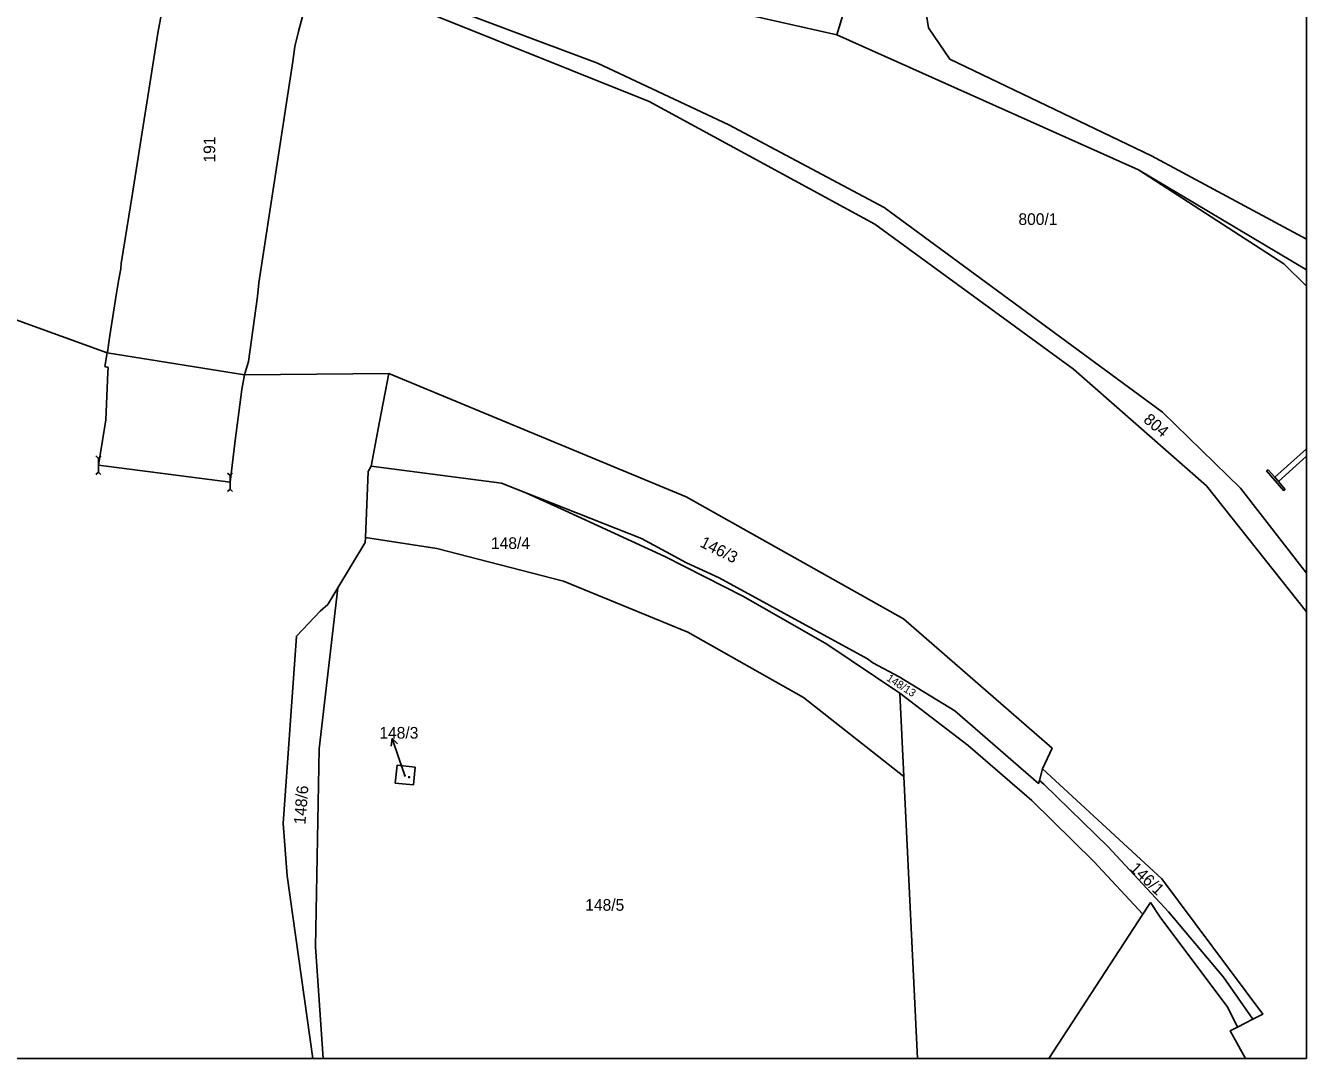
# Model space of a CAD drawing. Extents: x -598934 to -598196, y -1162208 to -1161502.
# Drawn here: x -598382.2 to -598195.6, y -1162207 to -1162056.4 of the extents above; entities that cross this region are included whole.
import ezdxf

# ---------------------------------------------------------------- set-up
doc = ezdxf.new("R2010")
doc.units = 0
for name, color, linetype in [('KN_CAR_KR', 7, 'Continuous'), ('KN_KULTURY', 7, 'Continuous'), ('KN_PARC_CIS_POM', 7, 'Continuous'), ('KN_PARC_CIS_POZ', 7, 'Continuous'), ('KN_PARC_CIS_STAV', 7, 'Continuous'), ('KN_PARC_PLOCHA', 7, 'Continuous'), ('PARC_C_SIPKA', 7, 'Continuous'), ('parcely_l', 7, 'Continuous')]:
    doc.layers.add(name, color=color, linetype=linetype)

msp = doc.modelspace()

# ---------------------------------------------------------------- linework, layer by layer
at = {"layer": 'KN_CAR_KR'}
for points in [[(-598220.05, -1162077.44), (-598198.85, -1162091.15)], [(-598198.85, -1162091.15), (-598195.56, -1162094.37)], [(-598370.68, -1162106.09), (-598370.34, -1162104.09)], [(-598370.22, -1162106.23), (-598370.68, -1162106.09)], [(-598370.53, -1162113.86), (-598370.27, -1162106.96)], [(-598370.27, -1162106.96), (-598370.22, -1162106.23)], [(-598350.7, -1162109.47), (-598350.35, -1162107.33)], [(-598351.7, -1162116.9), (-598350.7, -1162109.47)], [(-598370.53, -1162113.86), (-598370.72, -1162115.08)], [(-598370.72, -1162115.08), (-598371.63, -1162120.5)], [(-598352.44, -1162122.98), (-598351.7, -1162116.9)], [(-598195.56, -1162118.09), (-598200.16, -1162122.25)], [(-598371.63, -1162120.5), (-598352.44, -1162122.98)], [(-598199.63, -1162122.86), (-598195.56, -1162119.16)], [(-598201.39, -1162121.32), (-598201.11, -1162121.18)], [(-598198.86, -1162124.21), (-598201.39, -1162121.32)], [(-598201.11, -1162121.18), (-598200.16, -1162122.25)], [(-598200.16, -1162122.25), (-598199.63, -1162122.86)], [(-598199.63, -1162122.86), (-598198.65, -1162124.02)], [(-598198.65, -1162124.02), (-598198.86, -1162124.21)]]:
    msp.add_lwpolyline(points, dxfattribs=at)
at = {"layer": 'KN_KULTURY'}
for p, q in [((-598371.63, -1162121.5), (-598371.63, -1162119.5)), ((-598352.44, -1162123.98), (-598352.44, -1162121.98))]:
    msp.add_line(p, q, dxfattribs=at)
for points in [[(-598371.98, -1162119.15), (-598371.63, -1162119.5), (-598371.28, -1162119.15)], [(-598371.98, -1162121.85), (-598371.63, -1162121.5), (-598371.28, -1162121.85)], [(-598352.79, -1162121.63), (-598352.44, -1162121.98), (-598352.09, -1162121.63)], [(-598352.79, -1162124.33), (-598352.44, -1162123.98), (-598352.09, -1162124.33)]]:
    msp.add_lwpolyline(points, dxfattribs=at)
for radius in [0.09, 0.0398]:
    msp.add_circle((-598326.33, -1162165.97), radius, dxfattribs=at)
at = {"layer": 'KN_PARC_PLOCHA'}
for points in [[(-598195.56, -1162087.55), (-598218.14, -1162075.38), (-598247.54, -1162061.32), (-598250.65, -1162056.75), (-598252, -1162047.98), (-598239.76, -1162045.66), (-598222.81, -1162042.25), (-598205.98, -1162037.63), (-598195.56, -1162034.22)], [(-598263.99, -1162057.76), (-598220.05, -1162077.44), (-598195.56, -1162092.01), (-598195.56, -1162136.23), (-598205.15, -1162123.82), (-598216.54, -1162112.76), (-598257.11, -1162082.94), (-598279.75, -1162070.87), (-598298.86, -1162061.88), (-598339.73, -1162046.53), (-598339.66, -1162046.05), (-598338.47, -1162039.46), (-598331.32, -1162040.94), (-598316.47, -1162043.58), (-598304.18, -1162046.54), (-598295.91, -1162047.3), (-598291.83, -1162048.73), (-598287.23, -1162050.26), (-598284.77, -1162051.1), (-598282.25, -1162051.96), (-598279.39, -1162053.09), (-598278.46, -1162054.52)], [(-598195.56, -1162136.23), (-598195.56, -1162141.85), (-598210.14, -1162123.52), (-598229.5, -1162106.51), (-598258.47, -1162085.36), (-598291.34, -1162067.48), (-598324.91, -1162054), (-598340.53, -1162050.35), (-598339.73, -1162046.53), (-598298.86, -1162061.88), (-598279.75, -1162070.87), (-598257.11, -1162082.94), (-598216.54, -1162112.76), (-598205.15, -1162123.82)], [(-598195.56, -1162087.55), (-598195.56, -1162092.01), (-598220.05, -1162077.44), (-598263.99, -1162057.76), (-598261.41, -1162049.25), (-598252, -1162047.98), (-598250.65, -1162056.75), (-598247.54, -1162061.32), (-598218.14, -1162075.38)], [(-598234, -1162164.77), (-598234.47, -1162166.45), (-598234.59, -1162166.88), (-598246.81, -1162156.31), (-598254.92, -1162151.32), (-598258.74, -1162149.32), (-598259.51, -1162148.74), (-598281.14, -1162136.91), (-598285.89, -1162134.72), (-598292.46, -1162131.16), (-598309.31, -1162124.51), (-598312.87, -1162123.1), (-598331.85, -1162120.61), (-598330.66, -1162114.17), (-598329.28, -1162107.14), (-598285.97, -1162125.12), (-598254.28, -1162142.9), (-598232.63, -1162161.76)], [(-598309.31, -1162124.51), (-598303.63, -1162127.1), (-598289.09, -1162133.8), (-598277.62, -1162139.65), (-598265.44, -1162146.56), (-598254.82, -1162153.71), (-598254.23, -1162165.87), (-598268.85, -1162154.33), (-598285.74, -1162144.81), (-598303.83, -1162137.38), (-598322.31, -1162132.64), (-598332.7, -1162131.01), (-598332.32, -1162121.43), (-598331.85, -1162120.61), (-598312.87, -1162123.1)], [(-598234.47, -1162166.45), (-598233.83, -1162166.99), (-598224.46, -1162176.14), (-598215.64, -1162185.62), (-598207.62, -1162195.12), (-598203.37, -1162201.25), (-598205.62, -1162202.39), (-598207.02, -1162199.53), (-598216.85, -1162186.38), (-598218.3, -1162184.26), (-598219.4, -1162185.95), (-598226.54, -1162178.27), (-598235.59, -1162169.37), (-598244.87, -1162161.35), (-598254.82, -1162153.71), (-598265.44, -1162146.56), (-598277.62, -1162139.65), (-598289.09, -1162133.8), (-598303.63, -1162127.1), (-598309.31, -1162124.51), (-598292.46, -1162131.16), (-598285.89, -1162134.72), (-598281.14, -1162136.91), (-598259.51, -1162148.74), (-598258.74, -1162149.32), (-598254.92, -1162151.32), (-598246.81, -1162156.31), (-598234.59, -1162166.88)], [(-598254.23, -1162165.87), (-598252.26, -1162206.96), (-598338.86, -1162206.96), (-598339.99, -1162190.7), (-598339.45, -1162161.86), (-598336.71, -1162138.36), (-598332.73, -1162131.76), (-598332.7, -1162131.01), (-598322.31, -1162132.64), (-598303.83, -1162137.38), (-598285.74, -1162144.81), (-598268.85, -1162154.33)], [(-598338.86, -1162206.96), (-598340.39, -1162206.96), (-598344.1, -1162180.34), (-598344.68, -1162172.7), (-598342.77, -1162145.4), (-598339.32, -1162141.77), (-598338.19, -1162140.82), (-598336.71, -1162138.36), (-598339.45, -1162161.86), (-598339.99, -1162190.7)], [(-598219.4, -1162185.95), (-598233.08, -1162206.96), (-598252.26, -1162206.96), (-598254.23, -1162165.87), (-598254.82, -1162153.71), (-598244.87, -1162161.35), (-598235.59, -1162169.37), (-598226.54, -1162178.27)], [(-598325.47, -1162164.5), (-598325.72, -1162167.09), (-598328.36, -1162166.82), (-598328.1, -1162164.23)], [(-598325.47, -1162164.5), (-598328.1, -1162164.23), (-598328.36, -1162166.82), (-598325.72, -1162167.09)], [(-598203.37, -1162201.25), (-598207.62, -1162195.12), (-598215.64, -1162185.62), (-598224.46, -1162176.14), (-598233.83, -1162166.99), (-598234.47, -1162166.45), (-598234, -1162164.77), (-598216.64, -1162180.77), (-598201.91, -1162200.52)], [(-598205.62, -1162202.39), (-598206.66, -1162202.95), (-598204.42, -1162206.96), (-598233.08, -1162206.96), (-598219.4, -1162185.95), (-598218.3, -1162184.26), (-598216.85, -1162186.38), (-598207.02, -1162199.53)]]:
    msp.add_lwpolyline(points, close=True, dxfattribs=at)
for points in [[(-598406.5, -1162041.96), (-598368.98, -1162046.88), (-598369.04, -1162047.3), (-598369.12, -1162047.84), (-598369.89, -1162052.52), (-598362.27, -1162053.87), (-598362.95, -1162057.49), (-598364.73, -1162068.58), (-598364.81, -1162069.18), (-598366.55, -1162080.27), (-598366.66, -1162080.9), (-598368.3, -1162091.11), (-598368.37, -1162091.87), (-598368.64, -1162093.39), (-598368.97, -1162095.39), (-598369.94, -1162101.59), (-598370.19, -1162103.29), (-598370.24, -1162103.76), (-598370.34, -1162104.09), (-598387.71, -1162097.85)], [(-598261.41, -1162049.25), (-598263.99, -1162057.76), (-598278.46, -1162054.52)], [(-598341.1, -1162052.1), (-598342.48, -1162057.27), (-598343, -1162059.47), (-598343.29, -1162061.66), (-598348.24, -1162093.91), (-598348.45, -1162095.91), (-598349.77, -1162105.36), (-598350.35, -1162107.33), (-598370.34, -1162104.09), (-598370.24, -1162103.76), (-598370.19, -1162103.29), (-598369.94, -1162101.59), (-598368.97, -1162095.39), (-598368.64, -1162093.39), (-598368.37, -1162091.87), (-598368.3, -1162091.11), (-598366.66, -1162080.9), (-598366.55, -1162080.27), (-598364.81, -1162069.18), (-598364.73, -1162068.58), (-598362.95, -1162057.49), (-598362.27, -1162053.87)], [(-598324.91, -1162054), (-598291.34, -1162067.48), (-598258.47, -1162085.36), (-598229.5, -1162106.51), (-598210.14, -1162123.52), (-598195.56, -1162141.85), (-598195.56, -1162206.96), (-598204.42, -1162206.96), (-598206.66, -1162202.95), (-598205.62, -1162202.39), (-598203.37, -1162201.25), (-598201.91, -1162200.52), (-598216.64, -1162180.77), (-598234, -1162164.77), (-598232.63, -1162161.76), (-598254.28, -1162142.9), (-598285.97, -1162125.12), (-598329.28, -1162107.14), (-598350.35, -1162107.33), (-598349.77, -1162105.36), (-598348.45, -1162095.91), (-598348.24, -1162093.91), (-598343.29, -1162061.66), (-598343, -1162059.47), (-598342.48, -1162057.27), (-598341.1, -1162052.1)], [(-598387.71, -1162097.85), (-598370.34, -1162104.09), (-598350.35, -1162107.33), (-598329.28, -1162107.14), (-598330.66, -1162114.17), (-598331.85, -1162120.61), (-598332.32, -1162121.43), (-598332.7, -1162131.01), (-598332.73, -1162131.76), (-598336.71, -1162138.36), (-598338.19, -1162140.82), (-598339.32, -1162141.77), (-598342.77, -1162145.4), (-598344.68, -1162172.7), (-598344.1, -1162180.34), (-598340.39, -1162206.96), (-598402.41, -1162206.96)]]:
    msp.add_lwpolyline(points, dxfattribs=at)
at = {"layer": 'PARC_C_SIPKA'}
for points in [[(-598328.98, -1162161.45), (-598328.83, -1162160.35), (-598328.03, -1162161.13)], [(-598326.93, -1162165.85), (-598327.85, -1162163.18), (-598328.83, -1162160.35)]]:
    msp.add_lwpolyline(points, dxfattribs=at)
at = {"layer": 'parcely_l'}
for points in [[(-598195.56, -1162034.22), (-598195.56, -1162087.55)], [(-598338.47, -1162039.46), (-598331.32, -1162040.94), (-598316.47, -1162043.58), (-598304.18, -1162046.54), (-598295.91, -1162047.3), (-598291.83, -1162048.73), (-598287.23, -1162050.26), (-598284.77, -1162051.1), (-598282.25, -1162051.96), (-598279.39, -1162053.09), (-598278.46, -1162054.52), (-598263.99, -1162057.76)], [(-598339.73, -1162046.53), (-598298.86, -1162061.88), (-598279.75, -1162070.87), (-598257.11, -1162082.94), (-598216.54, -1162112.76), (-598205.15, -1162123.82), (-598195.56, -1162136.23)], [(-598252, -1162047.98), (-598261.41, -1162049.25), (-598263.99, -1162057.76)], [(-598252, -1162047.98), (-598250.65, -1162056.75), (-598247.54, -1162061.32), (-598218.14, -1162075.38), (-598195.56, -1162087.55)], [(-598350.35, -1162107.33), (-598349.77, -1162105.36), (-598348.45, -1162095.91), (-598348.24, -1162093.91), (-598343.29, -1162061.66), (-598343, -1162059.47), (-598342.48, -1162057.27), (-598341.1, -1162052.1), (-598340.53, -1162050.35)], [(-598195.56, -1162141.85), (-598210.14, -1162123.52), (-598229.5, -1162106.51), (-598258.47, -1162085.36), (-598291.34, -1162067.48), (-598324.91, -1162054), (-598340.53, -1162050.35)], [(-598362.27, -1162053.87), (-598362.95, -1162057.49), (-598364.73, -1162068.58), (-598364.81, -1162069.18), (-598366.55, -1162080.27), (-598366.66, -1162080.9), (-598368.3, -1162091.11), (-598368.37, -1162091.87), (-598368.64, -1162093.39), (-598368.97, -1162095.39), (-598369.94, -1162101.59), (-598370.19, -1162103.29), (-598370.24, -1162103.76), (-598370.34, -1162104.09)], [(-598263.99, -1162057.76), (-598220.05, -1162077.44), (-598195.56, -1162092.01)], [(-598195.56, -1162087.55), (-598195.56, -1162092.01)], [(-598195.56, -1162092.01), (-598195.56, -1162136.23)], [(-598370.34, -1162104.09), (-598387.71, -1162097.85)], [(-598350.35, -1162107.33), (-598370.34, -1162104.09)], [(-598329.28, -1162107.14), (-598350.35, -1162107.33)], [(-598331.85, -1162120.61), (-598330.66, -1162114.17), (-598329.28, -1162107.14)], [(-598234, -1162164.77), (-598232.63, -1162161.76), (-598254.28, -1162142.9), (-598285.97, -1162125.12), (-598329.28, -1162107.14)], [(-598332.7, -1162131.01), (-598332.32, -1162121.43), (-598331.85, -1162120.61)], [(-598309.31, -1162124.51), (-598312.87, -1162123.1), (-598331.85, -1162120.61)], [(-598234.47, -1162166.45), (-598234.59, -1162166.88), (-598246.81, -1162156.31), (-598254.92, -1162151.32), (-598258.74, -1162149.32), (-598259.51, -1162148.74), (-598281.14, -1162136.91), (-598285.89, -1162134.72), (-598292.46, -1162131.16), (-598309.31, -1162124.51)], [(-598254.82, -1162153.71), (-598265.44, -1162146.56), (-598277.62, -1162139.65), (-598289.09, -1162133.8), (-598303.63, -1162127.1), (-598309.31, -1162124.51)], [(-598336.71, -1162138.36), (-598332.73, -1162131.76), (-598332.7, -1162131.01)], [(-598254.23, -1162165.87), (-598268.85, -1162154.33), (-598285.74, -1162144.81), (-598303.83, -1162137.38), (-598322.31, -1162132.64), (-598332.7, -1162131.01)], [(-598195.56, -1162136.23), (-598195.56, -1162141.85)], [(-598340.39, -1162206.96), (-598344.1, -1162180.34), (-598344.68, -1162172.7), (-598342.77, -1162145.4), (-598339.32, -1162141.77), (-598338.19, -1162140.82), (-598336.71, -1162138.36)], [(-598336.71, -1162138.36), (-598339.45, -1162161.86), (-598339.99, -1162190.7), (-598338.86, -1162206.96)], [(-598195.56, -1162141.85), (-598195.56, -1162206.96), (-598204.42, -1162206.96)], [(-598254.23, -1162165.87), (-598254.82, -1162153.71)], [(-598254.82, -1162153.71), (-598244.87, -1162161.35), (-598235.59, -1162169.37), (-598226.54, -1162178.27), (-598219.4, -1162185.95)], [(-598325.47, -1162164.5), (-598328.1, -1162164.23), (-598328.36, -1162166.82), (-598325.72, -1162167.09), (-598325.47, -1162164.5)], [(-598234.47, -1162166.45), (-598234, -1162164.77)], [(-598203.37, -1162201.25), (-598201.91, -1162200.52), (-598216.64, -1162180.77), (-598234, -1162164.77)], [(-598252.26, -1162206.96), (-598254.23, -1162165.87)], [(-598203.37, -1162201.25), (-598207.62, -1162195.12), (-598215.64, -1162185.62), (-598224.46, -1162176.14), (-598233.83, -1162166.99), (-598234.47, -1162166.45)], [(-598219.4, -1162185.95), (-598218.3, -1162184.26), (-598216.85, -1162186.38), (-598207.02, -1162199.53), (-598205.62, -1162202.39)], [(-598219.4, -1162185.95), (-598233.08, -1162206.96)], [(-598204.42, -1162206.96), (-598206.66, -1162202.95), (-598205.62, -1162202.39)], [(-598205.62, -1162202.39), (-598203.37, -1162201.25)], [(-598340.39, -1162206.96), (-598402.41, -1162206.96)], [(-598338.86, -1162206.96), (-598340.39, -1162206.96)], [(-598252.26, -1162206.96), (-598338.86, -1162206.96)], [(-598233.08, -1162206.96), (-598252.26, -1162206.96)], [(-598204.42, -1162206.96), (-598233.08, -1162206.96)]]:
    msp.add_lwpolyline(points, dxfattribs=at)

# ---------------------------------------------------------------- texts
at = {"layer": 'KN_PARC_CIS_POM'}
msp.add_text('148/3', height=0.2, dxfattribs=at).set_placement((-598327.4, -1162165.85))
at = {"layer": 'KN_PARC_CIS_POZ'}
for s, height, rotation, p in [('191', 1.7, 90, (-598354.6, -1162076.38)), ('804', 1.7, 319.4994, (-598219.44, -1162114.07)), ('146/3', 1.7, 333.4024, (-598284.08, -1162132.29)), ('148/13', 1.14, 326.8573, (-598256.86, -1162151.79)), ('148/6', 1.7, 85.5006, (-598341.46, -1162172.92)), ('146/1', 1.7, 316.617, (-598221.41, -1162179.42))]:
    msp.add_text(s, height=height, rotation=rotation, dxfattribs=at).set_placement(p)
for s, p in [('800/1', (-598237.53, -1162085.47)), ('148/4', (-598314.41, -1162132.7)), ('148/5', (-598300.67, -1162185.44))]:
    msp.add_text(s, height=1.7, dxfattribs=at).set_placement(p)
at = {"layer": 'KN_PARC_CIS_STAV'}
msp.add_text('148/3', height=1.7, dxfattribs=at).set_placement((-598330.68, -1162160.35))

doc.saveas('drawing.dxf')
